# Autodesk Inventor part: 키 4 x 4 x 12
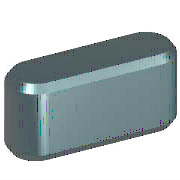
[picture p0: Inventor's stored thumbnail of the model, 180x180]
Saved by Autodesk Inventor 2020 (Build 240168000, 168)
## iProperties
Created: 2012-02
Part Number: 키 4 x 4 x 12
Material: 알루미늄 6061
Description: 키 및 해당 키홈
Document SubType Name: Modeling
Standard: KS B 1311
Designer: mduedu
Standards Organization: KS
Language: ko-KR
Size Designation: 4 x 4 x 12
Categories: <MemberInstance><Categories><Category DisplayName="샤프트 부품" InternalName="7f7aeb1f-a693-4053-b835-cee3144e0d98" Mnemonic="SHFT"><Category DisplayName="키" Interna
Density: 2.7 g/cm^3
Mass: 0.476585 g
Surface Area: 1.94869 cm^2
Volume: 0.176513 cm^3
Appearance: 노란색
IsCustomPart: 1
Author: mduedu
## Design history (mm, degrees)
workplane "Work Plane1"
workplane "Work Plane2"
sketch "스케치1"
  geometry: L1 (2, 2)-(10, 2); L2 (10, -2)-(2, -2); L3 (0, 9.4)-(0, -7.4) reference; L4 (-5, 0)-(30, 0) reference; L5 (12, 0)-(12, 7); A1 r 2 centre (2, 0) between (2, 2) and (2, -2); A2 r 2 centre (10, 0) between (10, -2) and (10, 2)
  constraints: 6 end point, 5 point on circle, 4 tangent, 3 point on line, 2 centre point, 1 horizontal, 1 parallel, 1 perpendicular
  dimensions: "d0" = 2 radius of A1 (= 0.5 x PB); "d13" = 2 radius of A2 (= 0.5 x PB); "d14" = 12 distance between parallel lines of L5 L3 (= NLG)
extrude "본체1" new body sketch "스케치1" taper "d3" = 0 deg; stored distance "d4" = 10
workplane "Work Plane3"
body "Solid1"
chamfer "모따기1" distance "d8" = 0.25 (= PHH); stored, may be unused: second distance "d9" = 0.25 (= PHH), angle "d15" = 45 deg
other parameters: "d1" = -2.5 (= -PNT), "d2" = 1.5 (= PH - PNT), "NLG" = 12 [user parameter; used in 3 equation terms], "PB" = 4 [user parameter; used in 2 equation terms], "PNT" = 2.5 [user parameter; used in 2 equation terms], "PH" = 4 [user parameter; used in 1 equation term], "PHH" = 0.25 [user parameter; used in 2 equation terms], "d10" = 0, "d16" = 0, "d17" = 0, "d18" = 0, "PLB2" = 12 (= NLG) [user parameter], "WDMAX" = 12 [user parameter], "PLB1" = 12 (= NLG) [user parameter], "RR" = 0.08 [user parameter], "PUEB" = 1.8 [user parameter]
